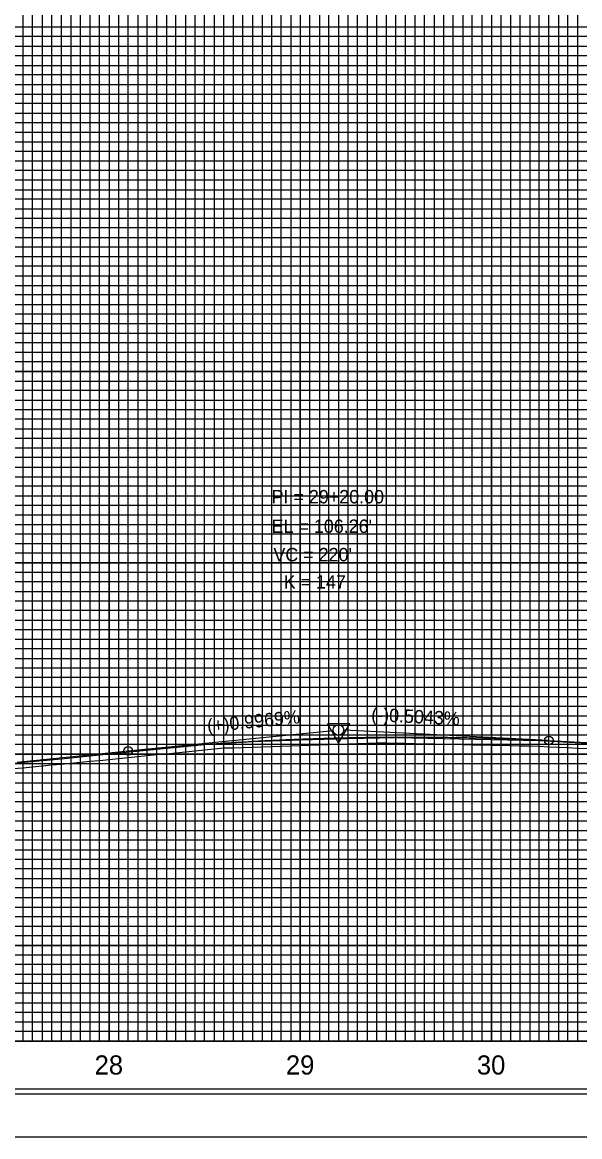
# Model space of a CAD drawing. Extents: x 2345490 to 2436403, y 465165 to 573888.
# Drawn here: x 2383521 to 2383813, y 515088 to 515670 of the extents above; entities that cross this region are included whole.
import ezdxf

# ---------------------------------------------------------------- set-up
doc = ezdxf.new("R2010")
doc.units = 0
for name, color, linetype in [('Old_Level_1', 7, 'Continuous'), ('Old_Level_18', 7, 'Continuous'), ('Old_Level_2', 7, 'Continuous'), ('Old_Level_41', 7, 'Continuous'), ('Old_Level_42', 7, 'Continuous'), ('Old_Level_43', 7, 'Continuous'), ('Old_Level_50', 7, 'Continuous'), ('Old_Level_51', 7, 'Continuous'), ('Old_Level_57', 7, 'Continuous'), ('Old_Level_61', 7, 'Continuous'), ('Old_Level_62', 7, 'Continuous'), ('Old_Level_63', 7, 'Continuous')]:
    doc.layers.add(name, color=color, linetype=linetype)

msp = doc.modelspace()

# ---------------------------------------------------------------- linework, layer by layer
at = {"layer": 'Old_Level_1'}
for points in [[(2383516.799, 515279.94525), (2383521.799, 515280.41975), (2383526.799, 515280.89425), (2383531.799, 515281.36875), (2383536.799, 515281.84325), (2383541.799, 515282.31775), (2383546.799, 515282.76325), (2383551.799, 515283.24025), (2383556.799, 515283.74175), (2383561.799, 515284.2435), (2383566.799, 515284.745), (2383571.799, 515285.2465), (2383576.799, 515285.7355), (2383581.799, 515286.2315), (2383586.799, 515286.73325), (2383591.799, 515287.23475), (2383596.799, 515287.73625), (2383601.799, 515288.23775), (2383606.799, 515288.72675), (2383611.799, 515289.22275), (2383616.799, 515289.72425), (2383621.799, 515290.226), (2383626.799, 515290.71175), (2383631.799, 515290.8705), (2383636.799, 515291.03425), (2383641.799, 515291.198), (2383646.799, 515291.3615), (2383651.799, 515291.52525), (2383656.799, 515291.68875), (2383661.799, 515291.8475), (2383666.799, 515292.011), (2383671.799, 515292.17475), (2383676.799, 515292.3385), (2383681.799, 515292.502), (2383686.799, 515292.66575), (2383691.799, 515292.8295), (2383696.799, 515292.993), (2383701.799, 515293.15675), (2383706.799, 515293.3205), (2383711.799, 515293.35625), (2383716.799, 515293.25325), (2383721.799, 515293.15025), (2383726.799, 515293.04725), (2383731.799, 515292.944), (2383736.799, 515292.841), (2383741.799, 515292.73225), (2383746.799, 515292.62925), (2383751.799, 515292.52625), (2383756.799, 515292.42325), (2383761.799, 515292.32025), (2383766.799, 515292.21725)], [(2383766.799, 515292.21725), (2383771.799, 515292.10875), (2383776.799, 515292.00575), (2383781.799, 515291.90275), (2383786.799, 515291.79975), (2383791.799, 515291.61975), (2383796.799, 515291.379), (2383801.799, 515291.1385), (2383806.799, 515290.898), (2383811.799, 515290.6575), (2383816.799, 515290.41675)]]:
    msp.add_lwpolyline(points, dxfattribs=at)
at = {"layer": 'Old_Level_18'}
msp.add_lwpolyline([(2384616.79875, 516162.5265), (2383116.79875, 516162.5265), (2383116.79875, 515112.5265), (2384616.79875, 515112.5265)], close=True, dxfattribs=at)
at = {"layer": 'Old_Level_2'}
for p, q in [((2383576.799, 515289.161), (2383684.06275, 515299.85375)), ((2383796.799, 515294.57875), (2383689.54575, 515299.988)), ((2383796.799, 515294.57875), (2383841.799, 515292.30925)), ((2383518.799, 515283.379), (2383576.799, 515289.161))]:
    msp.add_line(p, q, dxfattribs=at)
msp.add_lwpolyline([(2383692.72475, 515303.411), (2383680.98225, 515303.3965), (2383686.86575, 515293.27825)], close=True, dxfattribs=at)
for centre, radius in [((2383686.799, 515300.1265), 2.75), ((2383686.799, 515300.1265), 2.75), ((2383576.799, 515289.161), 2.25), ((2383796.799, 515294.57875), 2.25)]:
    msp.add_circle(centre, radius, dxfattribs=at)
msp.add_spline([(2383576.799, 515289.161), (2383581.199, 515289.593), (2383585.599, 515290.01175), (2383589.999, 515290.4175), (2383594.399, 515290.80975), (2383598.799, 515291.189), (2383603.199, 515291.555), (2383607.599, 515291.90775), (2383611.999, 515292.24725), (2383616.399, 515292.5735), (2383620.799, 515292.88675), (2383625.199, 515293.1865), (2383629.599, 515293.47325), (2383633.999, 515293.74675), (2383638.399, 515294.007), (2383642.799, 515294.25425), (2383647.199, 515294.488), (2383651.599, 515294.70875), (2383655.999, 515294.916), (2383660.399, 515295.11025), (2383664.799, 515295.29125), (2383669.199, 515295.45925), (2383673.599, 515295.61375), (2383677.999, 515295.75525), (2383682.399, 515295.88325), (2383686.799, 515295.99825), (2383691.199, 515296.1), (2383695.599, 515296.1885), (2383699.999, 515296.264), (2383704.399, 515296.326), (2383708.799, 515296.375), (2383713.199, 515296.4105), (2383717.599, 515296.433), (2383721.999, 515296.44225), (2383726.399, 515296.4385), (2383730.799, 515296.42125), (2383735.199, 515296.391), (2383739.599, 515296.34725), (2383743.999, 515296.2905), (2383748.399, 515296.2205), (2383752.799, 515296.1375), (2383757.199, 515296.041), (2383761.599, 515295.93125), (2383765.999, 515295.8085), (2383770.399, 515295.6725), (2383774.799, 515295.52325), (2383779.199, 515295.36075), (2383783.599, 515295.185), (2383787.999, 515294.99625), (2383792.399, 515294.794), (2383796.799, 515294.57875)], degree=3, dxfattribs=at)
at = {"layer": 'Old_Level_41'}
msp.add_line((2384616.79875, 515137.5265), (2383116.79875, 515137.5265), dxfattribs=at)
for points in [[(2383541.79875, 516162.5265), (2383541.79875, 515137.5265), (2383591.79875, 515137.5265), (2383591.79875, 516162.5265)], [(2383566.79875, 516162.5265), (2383566.79875, 515137.5265), (2383616.79875, 515137.5265), (2383616.79875, 516162.5265)], [(2383641.79875, 516162.5265), (2383641.79875, 515137.5265), (2383691.79875, 515137.5265), (2383691.79875, 516162.5265)], [(2383666.79875, 516162.5265), (2383666.79875, 515137.5265), (2383716.79875, 515137.5265), (2383716.79875, 516162.5265)], [(2383741.79875, 516162.5265), (2383741.79875, 515137.5265), (2383791.79875, 515137.5265), (2383791.79875, 516162.5265)], [(2383766.79875, 516162.5265), (2383766.79875, 515137.5265), (2383816.79875, 515137.5265)], [(2384616.79875, 515662.5265), (2383116.79875, 515662.5265), (2383116.79875, 515612.5265), (2384616.79875, 515612.5265)], [(2384616.79875, 515562.5265), (2383116.79875, 515562.5265), (2383116.79875, 515512.5265), (2384616.79875, 515512.5265)], [(2384616.79875, 515487.5265), (2383116.79875, 515487.5265), (2383116.79875, 515537.5265), (2384616.79875, 515537.5265)], [(2384616.79875, 515462.5265), (2383116.79875, 515462.5265), (2383116.79875, 515412.5265), (2384616.79875, 515412.5265)], [(2384616.79875, 515387.5265), (2383116.79875, 515387.5265), (2383116.79875, 515437.5265), (2384616.79875, 515437.5265)], [(2384616.79875, 515362.5265), (2383116.79875, 515362.5265), (2383116.79875, 515312.5265), (2384616.79875, 515312.5265)], [(2384616.79875, 515262.5265), (2383116.79875, 515262.5265), (2383116.79875, 515212.5265), (2384616.79875, 515212.5265)], [(2384616.79875, 515187.5265), (2383116.79875, 515187.5265), (2383116.79875, 515237.5265), (2384616.79875, 515237.5265)], [(2384616.79875, 515162.5265), (2383116.79875, 515162.5265)]]:
    msp.add_lwpolyline(points, dxfattribs=at)
at = {"layer": 'Old_Level_42'}
for points in [[(2384616.79875, 515587.5265), (2383116.79875, 515587.5265), (2383116.79875, 515637.5265), (2384616.79875, 515637.5265)], [(2384616.79875, 515287.5265), (2383116.79875, 515287.5265), (2383116.79875, 515337.5265), (2384616.79875, 515337.5265)]]:
    msp.add_lwpolyline(points, dxfattribs=at)
at = {"layer": 'Old_Level_43'}
for points in [[(2383521.79875, 516162.5265), (2383521.79875, 515137.5265), (2383526.79875, 515137.5265), (2383526.79875, 516162.5265)], [(2383531.79875, 516162.5265), (2383531.79875, 515137.5265), (2383536.79875, 515137.5265), (2383536.79875, 516162.5265)], [(2383546.79875, 516162.5265), (2383546.79875, 515137.5265), (2383551.79875, 515137.5265), (2383551.79875, 516162.5265)], [(2383556.79875, 516162.5265), (2383556.79875, 515137.5265), (2383561.79875, 515137.5265), (2383561.79875, 516162.5265)], [(2383571.79875, 516162.5265), (2383571.79875, 515137.5265), (2383576.79875, 515137.5265), (2383576.79875, 516162.5265)], [(2383581.79875, 516162.5265), (2383581.79875, 515137.5265), (2383586.79875, 515137.5265), (2383586.79875, 516162.5265)], [(2383596.79875, 516162.5265), (2383596.79875, 515137.5265), (2383601.79875, 515137.5265), (2383601.79875, 516162.5265)], [(2383606.79875, 516162.5265), (2383606.79875, 515137.5265), (2383611.79875, 515137.5265), (2383611.79875, 516162.5265)], [(2383621.79875, 516162.5265), (2383621.79875, 515137.5265), (2383626.79875, 515137.5265), (2383626.79875, 516162.5265)], [(2383631.79875, 516162.5265), (2383631.79875, 515137.5265), (2383636.79875, 515137.5265), (2383636.79875, 516162.5265)], [(2383646.79875, 516162.5265), (2383646.79875, 515137.5265)], [(2383651.79875, 516162.5265), (2383651.79875, 515137.5265), (2383656.79875, 515137.5265), (2383656.79875, 516162.5265), (2383661.79875, 516162.5265), (2383661.79875, 515137.5265), (2383671.79875, 515137.5265), (2383671.79875, 516162.5265), (2383676.79875, 516162.5265), (2383676.79875, 515137.5265), (2383681.79875, 515137.5265), (2383681.79875, 516162.5265), (2383686.79875, 516162.5265), (2383686.79875, 515137.5265)], [(2383696.79875, 515137.5265), (2383696.79875, 516162.5265)], [(2383701.79875, 516162.5265), (2383701.79875, 515137.5265), (2383706.79875, 515137.5265), (2383706.79875, 516162.5265)], [(2383711.79875, 516162.5265), (2383711.79875, 515137.5265), (2383721.79875, 515137.5265), (2383721.79875, 516162.5265)], [(2383726.79875, 516162.5265), (2383726.79875, 515137.5265), (2383726.79875, 515137.5265), (2383731.79875, 515137.5265), (2383731.79875, 516162.5265)], [(2383736.79875, 516162.5265), (2383736.79875, 515137.5265), (2383746.79875, 515137.5265), (2383746.79875, 516162.5265)], [(2383751.79875, 516162.5265), (2383751.79875, 515137.5265), (2383756.79875, 515137.5265), (2383756.79875, 516162.5265)], [(2383761.79875, 516162.5265), (2383761.79875, 515137.5265), (2383771.79875, 515137.5265), (2383771.79875, 516162.5265)], [(2383776.79875, 516162.5265), (2383776.79875, 515137.5265), (2383781.79875, 515137.5265), (2383781.79875, 516162.5265)], [(2383786.79875, 516162.5265), (2383786.79875, 515137.5265), (2383796.79875, 515137.5265), (2383796.79875, 516162.5265)], [(2383801.79875, 516162.5265), (2383801.79875, 515137.5265), (2383806.79875, 515137.5265), (2383806.79875, 516162.5265)], [(2383811.79875, 516162.5265), (2383811.79875, 515137.5265), (2383821.79875, 515137.5265)], [(2384566.79875, 515667.5265), (2383166.79875, 515667.5265), (2383166.79875, 515657.5265), (2384566.79875, 515657.5265)], [(2384566.79875, 515652.5265), (2383166.79875, 515652.5265), (2383166.79875, 515647.5265), (2384566.79875, 515647.5265)], [(2384566.79875, 515642.5265), (2383166.79875, 515642.5265)], [(2383166.79875, 515632.5265), (2384566.79875, 515632.5265)], [(2384566.79875, 515627.5265), (2383166.79875, 515627.5265), (2383166.79875, 515622.5265), (2384566.79875, 515622.5265)], [(2384566.79875, 515617.5265), (2383166.79875, 515617.5265), (2383166.79875, 515607.5265), (2384566.79875, 515607.5265)], [(2384566.79875, 515602.5265), (2383166.79875, 515602.5265), (2383166.79875, 515597.5265), (2384566.79875, 515597.5265)], [(2384566.79875, 515592.5265), (2383166.79875, 515592.5265), (2383166.79875, 515582.5265), (2384566.79875, 515582.5265)], [(2384566.79875, 515577.5265), (2383166.79875, 515577.5265), (2383166.79875, 515572.5265), (2384566.79875, 515572.5265)], [(2384566.79875, 515567.5265), (2383166.79875, 515567.5265), (2383166.79875, 515557.5265), (2384566.79875, 515557.5265)], [(2384566.79875, 515552.5265), (2383166.79875, 515552.5265), (2383166.79875, 515547.5265), (2384566.79875, 515547.5265)], [(2384566.79875, 515542.5265), (2383166.79875, 515542.5265), (2383166.79875, 515532.5265), (2384566.79875, 515532.5265)], [(2384566.79875, 515527.5265), (2383166.79875, 515527.5265), (2383166.79875, 515522.5265), (2384566.79875, 515522.5265)], [(2384566.79875, 515517.5265), (2383166.79875, 515517.5265), (2383166.79875, 515507.5265), (2384566.79875, 515507.5265)], [(2384566.79875, 515502.5265), (2383166.79875, 515502.5265), (2383166.79875, 515497.5265), (2384566.79875, 515497.5265)], [(2384566.79875, 515492.5265), (2383166.79875, 515492.5265), (2383166.79875, 515482.5265), (2384566.79875, 515482.5265)], [(2384566.79875, 515477.5265), (2383166.79875, 515477.5265), (2383166.79875, 515472.5265), (2384566.79875, 515472.5265)], [(2384566.79875, 515467.5265), (2383166.79875, 515467.5265), (2383166.79875, 515457.5265), (2384566.79875, 515457.5265)], [(2384566.79875, 515452.5265), (2383166.79875, 515452.5265), (2383166.79875, 515447.5265), (2384566.79875, 515447.5265)], [(2384566.79875, 515442.5265), (2383166.79875, 515442.5265), (2383166.79875, 515432.5265), (2384566.79875, 515432.5265)], [(2384566.79875, 515427.5265), (2383166.79875, 515427.5265), (2383166.79875, 515422.5265), (2384566.79875, 515422.5265)], [(2384566.79875, 515417.5265), (2383166.79875, 515417.5265), (2383166.79875, 515407.5265), (2384566.79875, 515407.5265)], [(2384566.79875, 515402.5265), (2383166.79875, 515402.5265), (2383166.79875, 515397.5265), (2384566.79875, 515397.5265)], [(2384566.79875, 515392.5265), (2383166.79875, 515392.5265), (2383166.79875, 515382.5265), (2384566.79875, 515382.5265)], [(2384566.79875, 515377.5265), (2383166.79875, 515377.5265), (2383166.79875, 515372.5265), (2384566.79875, 515372.5265)], [(2384566.79875, 515367.5265), (2383166.79875, 515367.5265), (2383166.79875, 515357.5265), (2384566.79875, 515357.5265)], [(2384566.79875, 515352.5265), (2383166.79875, 515352.5265), (2383166.79875, 515347.5265), (2384566.79875, 515347.5265)], [(2384566.79875, 515342.5265), (2383166.79875, 515342.5265)], [(2383166.79875, 515332.5265), (2384566.79875, 515332.5265)], [(2384566.79875, 515327.5265), (2383166.79875, 515327.5265), (2383166.79875, 515322.5265), (2384566.79875, 515322.5265)], [(2384566.79875, 515317.5265), (2383166.79875, 515317.5265)], [(2383166.79875, 515307.5265), (2384566.79875, 515307.5265)], [(2384566.79875, 515302.5265), (2383166.79875, 515302.5265), (2383166.79875, 515297.5265), (2384566.79875, 515297.5265)], [(2384566.79875, 515292.5265), (2383166.79875, 515292.5265), (2383166.79875, 515282.5265), (2384566.79875, 515282.5265)], [(2384566.79875, 515277.5265), (2383166.79875, 515277.5265), (2383166.79875, 515272.5265), (2384566.79875, 515272.5265)], [(2384566.79875, 515267.5265), (2383166.79875, 515267.5265), (2383166.79875, 515257.5265), (2384566.79875, 515257.5265)], [(2384566.79875, 515252.5265), (2383166.79875, 515252.5265), (2383166.79875, 515247.5265), (2384566.79875, 515247.5265)], [(2384566.79875, 515242.5265), (2383166.79875, 515242.5265), (2383166.79875, 515232.5265), (2384566.79875, 515232.5265)], [(2384566.79875, 515227.5265), (2383166.79875, 515227.5265), (2383166.79875, 515222.5265), (2384566.79875, 515222.5265)], [(2384566.79875, 515217.5265), (2383166.79875, 515217.5265), (2383166.79875, 515207.5265), (2384566.79875, 515207.5265)], [(2384566.79875, 515202.5265), (2383166.79875, 515202.5265), (2383166.79875, 515197.5265), (2384566.79875, 515197.5265)], [(2384566.79875, 515192.5265), (2383166.79875, 515192.5265), (2383166.79875, 515182.5265), (2384566.79875, 515182.5265)], [(2384566.79875, 515177.5265), (2383166.79875, 515177.5265), (2383166.79875, 515172.5265), (2384566.79875, 515172.5265)], [(2384566.79875, 515167.5265), (2383166.79875, 515167.5265), (2383166.79875, 515157.5265), (2384566.79875, 515157.5265)], [(2384566.79875, 515152.5265), (2383166.79875, 515152.5265), (2383166.79875, 515147.5265), (2384566.79875, 515147.5265)], [(2384566.79875, 515142.5265), (2383166.79875, 515142.5265)]]:
    msp.add_lwpolyline(points, dxfattribs=at)
at = {"layer": 'Old_Level_50'}
msp.add_lwpolyline([(2384629.29875, 516165.0765), (2382962.79875, 516165.0765), (2382962.79875, 515109.9765), (2384629.29875, 515109.9765)], close=True, dxfattribs=at)
at = {"layer": 'Old_Level_51'}
msp.add_lwpolyline([(2384633.79875, 516187.5265), (2382949.79875, 516187.5265), (2382949.79875, 515087.5265), (2384633.79875, 515087.5265)], close=True, dxfattribs=at)
at = {"layer": 'Old_Level_57'}
for p, q in [((2381716.79925, 515537.52675), (2386366.79875, 515537.52675)), ((2383566.79875, 515137.52675), (2383566.79875, 515537.52675)), ((2383566.79875, 515137.62675), (2383566.79875, 515537.52675)), ((2383566.79875, 515137.62675), (2383566.79875, 515537.52675)), ((2383666.79875, 515137.52675), (2383666.79875, 515537.52675)), ((2383666.79875, 515137.62675), (2383666.79875, 515537.52675)), ((2383766.79875, 515137.52675), (2383766.79875, 515537.52675)), ((2383766.79875, 515137.62675), (2383766.79875, 515537.52675)), ((2381716.79925, 515487.52675), (2386366.79875, 515487.52675)), ((2381716.79925, 515437.52675), (2386366.79875, 515437.52675)), ((2381716.79925, 515387.52675), (2386366.79875, 515387.52675)), ((2381716.79925, 515337.52675), (2386366.79875, 515337.52675)), ((2381716.79925, 515287.52675), (2386366.79875, 515287.52675)), ((2381716.79925, 515237.52675), (2386366.79875, 515237.52675)), ((2381716.799, 515187.52675), (2386366.79875, 515187.52675)), ((2381716.79925, 515137.52675), (2386366.79875, 515137.52675))]:
    msp.add_line(p, q, dxfattribs=at)
at = {"layer": 'Old_Level_61'}
msp.add_lwpolyline([(2383516.799, 515282.71575), (2383541.799, 515285.099), (2383566.799, 515287.57775), (2383591.799, 515290.08575), (2383616.799, 515292.594), (2383641.799, 515294.096), (2383666.799, 515294.922), (2383691.799, 515295.74825), (2383716.799, 515296.1965), (2383741.799, 515295.69425), (2383766.799, 515295.192), (2383791.799, 515294.58775), (2383816.799, 515293.29325)], dxfattribs=at)
at = {"layer": 'Old_Level_63'}
msp.add_line((2381766.79875, 515137.5265), (2386228.05125, 515137.5265), dxfattribs=at)

# ---------------------------------------------------------------- texts
at = {"layer": 'Old_Level_2'}
for s, height, p in [('PI = 29+20.00', 7.0000005, (2383651.79925, 515418.55875)), ("EL = 106.26'", 7.0000005, (2383651.799, 515403.1265)), ("VC = 220'", 7.000001, (2383652.75725, 515388.277)), ('K = 147', 7.000001, (2383658.15425, 515374.03875))]:
    msp.add_text(s, height=height, dxfattribs=at).set_placement(p)
for s, rotation, p in [('(+)0.9969%', 5.69286389, (2383618.44925, 515298.8115)), ('(-)0.5043%', 357.11274722, (2383703.792, 515304.82925))]:
    msp.add_text(s, height=7.000001, rotation=rotation, dxfattribs=at).set_placement(p)
at = {"layer": 'Old_Level_62'}
for s, p in [('28', (2383559.26725, 515120.0265)), ('29', (2383659.3095, 515120.0265)), ('30', (2383759.1855, 515120.0265))]:
    msp.add_text(s, height=10.000001, dxfattribs=at).set_placement(p)

doc.saveas('drawing.dxf')
